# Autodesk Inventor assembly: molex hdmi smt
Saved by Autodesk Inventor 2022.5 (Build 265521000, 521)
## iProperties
Created: 2024-12
Part Number: molex hdmi smt
Document SubType Name: Assembly
Designer: AdminForWorker
Title: molex hdmi smt v1
Author: AdminForWorker
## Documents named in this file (3)
- c:\worker\convert-fusion-r05-cosv3\tmp\job-1\35\temp\files\545dca92-a972-481a-9197-dd1a1176500e\molex hdmi smt v1.iam
- c:\worker\convert-fusion-r05-cosv3\tmp\job-1\35\temp\files\545dca92-a972-481a-9197-dd1a1176500e\Component2_2.ipt
- c:\worker\convert-fusion-r05-cosv3\tmp\job-1\35\temp\files\545dca92-a972-481a-9197-dd1a1176500e\Part122.ipt
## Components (2 placed, 2 different names)
1. Component2:1
2. Part122
